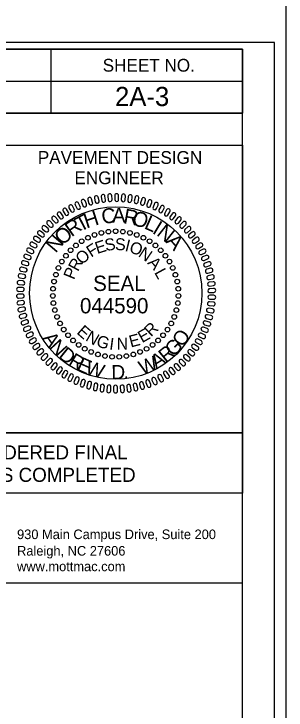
# Model space of a CAD drawing. Extents: x 1901718 to 1902220, y 193828 to 194187.
# Drawn here: x 1902123.6 to 1902134.24, y 193909.67 to 193936.89 of the extents above; entities that cross this region are included whole.
import ezdxf

# ---------------------------------------------------------------- set-up
doc = ezdxf.new("R2010")
doc.units = 0
for name, color, linetype in [('Default', 7, 'Continuous'), ('Old_Level_2', 7, 'Continuous'), ('Old_Level_42', 7, 'Continuous'), ('Scratch_Level_3', 7, 'Continuous'), ('Sheet Border Standard 30in CELL', 7, 'Continuous'), ('Sheet Data Field CELL', 7, 'Continuous'), ('Sheet Plot Border Inside CELL', 7, 'Continuous'), ('Sheet Plot Border Outside CELL', 7, 'Continuous'), ('Sheet Sticker Exception Certification CELL', 7, 'Continuous')]:
    doc.layers.add(name, color=color, linetype=linetype)

msp = doc.modelspace()

# ---------------------------------------------------------------- linework, layer by layer
at = {"layer": 'Default'}
for p, q in [((1902126.493, 193929.622), (1902126.535, 193929.479)), ((1902126.681, 193929.523), (1902126.638, 193929.667)), ((1902126.75, 193929.691), (1902126.784, 193929.545)), ((1902126.932, 193929.579), (1902126.898, 193929.724)), ((1902127.012, 193929.741), (1902127.035, 193929.593)), ((1902127.185, 193929.616), (1902127.162, 193929.764)), ((1902127.277, 193929.772), (1902127.289, 193929.623)), ((1902127.441, 193929.636), (1902127.428, 193929.786)), ((1902127.543, 193929.786), (1902127.545, 193929.636)), ((1902127.697, 193929.638), (1902127.695, 193929.788)), ((1902127.809, 193929.78), (1902127.801, 193929.631)), ((1902127.953, 193929.622), (1902127.961, 193929.772)), ((1902128.074, 193929.756), (1902128.056, 193929.608)), ((1902128.207, 193929.589), (1902128.225, 193929.737)), ((1902128.338, 193929.714), (1902128.308, 193929.567)), ((1902128.458, 193929.537), (1902128.487, 193929.685)), ((1902128.598, 193929.653), (1902128.558, 193929.509)), ((1902128.705, 193929.469), (1902128.744, 193929.614)), ((1902125.962, 193929.255), (1902125.89, 193929.386)), ((1902125.995, 193929.433), (1902126.058, 193929.297)), ((1902126.196, 193929.361), (1902126.132, 193929.497)), ((1902126.24, 193929.536), (1902126.294, 193929.396)), ((1902126.435, 193929.451), (1902126.383, 193929.591)), ((1902128.852, 193929.575), (1902128.803, 193929.433)), ((1902128.946, 193929.383), (1902128.996, 193929.525)), ((1902129.101, 193929.479), (1902129.042, 193929.34)), ((1902129.181, 193929.281), (1902129.241, 193929.418)), ((1902129.342, 193929.365), (1902129.274, 193929.232)), ((1902125.52, 193928.995), (1902125.431, 193929.115)), ((1902125.52, 193928.995), (1902125.431, 193929.115)), ((1902125.528, 193929.176), (1902125.609, 193929.05)), ((1902125.528, 193929.176), (1902125.609, 193929.05)), ((1902125.737, 193929.133), (1902125.656, 193929.259)), ((1902125.737, 193929.133), (1902125.656, 193929.259)), ((1902125.756, 193929.313), (1902125.829, 193929.181)), ((1902129.408, 193929.162), (1902129.477, 193929.295)), ((1902129.574, 193929.235), (1902129.497, 193929.107)), ((1902129.627, 193929.028), (1902129.705, 193929.156)), ((1902129.797, 193929.089), (1902129.712, 193928.966)), ((1902125.101, 193928.857), (1902125.2, 193928.744)), ((1902125.101, 193928.857), (1902125.2, 193928.744)), ((1902125.314, 193928.842), (1902125.216, 193928.957)), ((1902125.314, 193928.842), (1902125.216, 193928.957)), ((1902125.309, 193929.024), (1902125.399, 193928.904)), ((1902125.309, 193929.024), (1902125.399, 193928.904)), ((1902129.835, 193928.879), (1902129.922, 193929.001)), ((1902130.01, 193928.928), (1902129.915, 193928.812)), ((1902130.033, 193928.716), (1902130.128, 193928.832)), ((1902124.936, 193928.497), (1902124.824, 193928.596)), ((1902124.906, 193928.675), (1902125.011, 193928.57)), ((1902125.12, 193928.676), (1902125.014, 193928.783)), ((1902130.211, 193928.753), (1902130.108, 193928.643)), ((1902130.219, 193928.539), (1902130.322, 193928.649)), ((1902130.399, 193928.564), (1902130.288, 193928.462)), ((1902124.556, 193928.274), (1902124.675, 193928.184)), ((1902124.766, 193928.305), (1902124.647, 193928.396)), ((1902124.724, 193928.481), (1902124.836, 193928.383)), ((1902130.392, 193928.35), (1902130.502, 193928.452)), ((1902130.573, 193928.362), (1902130.456, 193928.268)), ((1902124.402, 193928.057), (1902124.527, 193927.975)), ((1902124.611, 193928.102), (1902124.485, 193928.184)), ((1902130.551, 193928.15), (1902130.668, 193928.244)), ((1902130.733, 193928.149), (1902130.609, 193928.063)), ((1902130.697, 193927.938), (1902130.819, 193928.024)), ((1902124.342, 193927.666), (1902124.207, 193927.729)), ((1902124.264, 193927.828), (1902124.395, 193927.756)), ((1902124.469, 193927.888), (1902124.338, 193927.961)), ((1902130.877, 193927.925), (1902130.749, 193927.848)), ((1902130.826, 193927.718), (1902130.955, 193927.794)), ((1902124.232, 193927.434), (1902124.092, 193927.488)), ((1902124.142, 193927.591), (1902124.277, 193927.528)), ((1902131.006, 193927.691), (1902130.872, 193927.624)), ((1902130.94, 193927.488), (1902131.074, 193927.556)), ((1902131.118, 193927.45), (1902130.979, 193927.391)), ((1902124.138, 193927.196), (1902123.995, 193927.24)), ((1902124.038, 193927.346), (1902124.177, 193927.292)), ((1902131.038, 193927.251), (1902131.177, 193927.31)), ((1902131.212, 193927.2), (1902131.07, 193927.152)), ((1902124.061, 193926.951), (1902123.915, 193926.985)), ((1902123.95, 193927.095), (1902124.093, 193927.05)), ((1902131.12, 193927.008), (1902131.262, 193927.056)), ((1902131.289, 193926.945), (1902131.144, 193926.907)), ((1902124.001, 193926.702), (1902123.852, 193926.726)), ((1902123.88, 193926.837), (1902124.026, 193926.803)), ((1902131.183, 193926.76), (1902131.328, 193926.799)), ((1902131.349, 193926.685), (1902131.202, 193926.657)), ((1902123.958, 193926.45), (1902123.809, 193926.463)), ((1902123.829, 193926.576), (1902123.977, 193926.552)), ((1902131.231, 193926.508), (1902131.377, 193926.536)), ((1902131.39, 193926.422), (1902131.241, 193926.404)), ((1902123.933, 193926.194), (1902123.784, 193926.197)), ((1902123.796, 193926.312), (1902123.944, 193926.298)), ((1902131.259, 193926.253), (1902131.408, 193926.271)), ((1902131.413, 193926.156), (1902131.263, 193926.149)), ((1902123.926, 193925.938), (1902123.777, 193925.931)), ((1902123.78, 193926.046), (1902123.93, 193926.042)), ((1902131.416, 193925.89), (1902131.266, 193925.893)), ((1902131.27, 193925.997), (1902131.42, 193926.005)), ((1902123.784, 193925.779), (1902123.934, 193925.786)), ((1902123.938, 193925.682), (1902123.789, 193925.664)), ((1902123.807, 193925.513), (1902123.956, 193925.531)), ((1902131.401, 193925.624), (1902131.252, 193925.638)), ((1902131.263, 193925.741), (1902131.413, 193925.738)), ((1902123.966, 193925.428), (1902123.819, 193925.4)), ((1902123.848, 193925.25), (1902123.995, 193925.278)), ((1902131.368, 193925.359), (1902131.22, 193925.383)), ((1902131.238, 193925.486), (1902131.387, 193925.472)), ((1902124.013, 193925.175), (1902123.868, 193925.137)), ((1902123.907, 193924.99), (1902124.052, 193925.028)), ((1902131.136, 193924.984), (1902131.282, 193924.95)), ((1902131.316, 193925.098), (1902131.17, 193925.132)), ((1902131.195, 193925.233), (1902131.344, 193925.21)), ((1902124.078, 193924.927), (1902123.935, 193924.879)), ((1902123.984, 193924.735), (1902124.126, 193924.783)), ((1902131.058, 193924.739), (1902131.202, 193924.695)), ((1902131.246, 193924.84), (1902131.104, 193924.885)), ((1902124.158, 193924.684), (1902124.02, 193924.626)), ((1902124.079, 193924.485), (1902124.217, 193924.544)), ((1902124.256, 193924.447), (1902124.122, 193924.379)), ((1902130.964, 193924.501), (1902131.104, 193924.447)), ((1902131.159, 193924.589), (1902131.019, 193924.643)), ((1902124.191, 193924.244), (1902124.325, 193924.311)), ((1902124.371, 193924.218), (1902124.242, 193924.141)), ((1902130.933, 193924.107), (1902130.802, 193924.18)), ((1902130.854, 193924.27), (1902130.99, 193924.206)), ((1902131.054, 193924.344), (1902130.919, 193924.407)), ((1902124.32, 193924.01), (1902124.448, 193924.087)), ((1902124.5, 193923.997), (1902124.377, 193923.911)), ((1902130.795, 193923.878), (1902130.669, 193923.96)), ((1902130.728, 193924.047), (1902130.859, 193923.973)), ((1902124.464, 193923.786), (1902124.587, 193923.872)), ((1902124.645, 193923.785), (1902124.529, 193923.692)), ((1902124.623, 193923.573), (1902124.741, 193923.667)), ((1902130.43, 193923.63), (1902130.549, 193923.54)), ((1902130.641, 193923.661), (1902130.522, 193923.751)), ((1902130.586, 193923.833), (1902130.711, 193923.751)), ((1902124.804, 193923.585), (1902124.695, 193923.483)), ((1902124.798, 193923.372), (1902124.908, 193923.474)), ((1902124.978, 193923.396), (1902124.875, 193923.287)), ((1902130.291, 193923.26), (1902130.185, 193923.366)), ((1902130.26, 193923.438), (1902130.373, 193923.34)), ((1902130.473, 193923.454), (1902130.36, 193923.553)), ((1902124.986, 193923.182), (1902125.089, 193923.292)), ((1902125.164, 193923.219), (1902125.069, 193923.103)), ((1902125.187, 193923.007), (1902125.281, 193923.123)), ((1902129.882, 193923.092), (1902129.98, 193922.979)), ((1902130.095, 193923.079), (1902129.997, 193923.192)), ((1902130.077, 193923.259), (1902130.182, 193923.153)), ((1902125.361, 193923.056), (1902125.274, 193922.934)), ((1902125.399, 193922.846), (1902125.485, 193922.969)), ((1902125.57, 193922.907), (1902125.492, 193922.779)), ((1902125.622, 193922.701), (1902125.699, 193922.828)), ((1902129.669, 193922.759), (1902129.587, 193922.885)), ((1902129.676, 193922.94), (1902129.766, 193922.82)), ((1902129.888, 193922.912), (1902129.797, 193923.031)), ((1902125.788, 193922.773), (1902125.72, 193922.64)), ((1902125.855, 193922.57), (1902125.924, 193922.704)), ((1902126.016, 193922.655), (1902125.956, 193922.516)), ((1902126.096, 193922.457), (1902126.155, 193922.595)), ((1902126.25, 193922.552), (1902126.201, 193922.411)), ((1902128.957, 193922.399), (1902128.903, 193922.539)), ((1902129.001, 193922.575), (1902129.064, 193922.439)), ((1902129.202, 193922.502), (1902129.139, 193922.638)), ((1902129.235, 193922.68), (1902129.307, 193922.549)), ((1902129.44, 193922.623), (1902129.368, 193922.754)), ((1902129.46, 193922.803), (1902129.541, 193922.677)), ((1902126.345, 193922.36), (1902126.394, 193922.503)), ((1902126.492, 193922.467), (1902126.453, 193922.322)), ((1902126.599, 193922.282), (1902126.638, 193922.427)), ((1902126.739, 193922.397), (1902126.71, 193922.251)), ((1902126.859, 193922.221), (1902126.888, 193922.368)), ((1902126.99, 193922.346), (1902126.971, 193922.198)), ((1902127.122, 193922.179), (1902127.141, 193922.327)), ((1902127.244, 193922.313), (1902127.236, 193922.163)), ((1902127.387, 193922.155), (1902127.396, 193922.305)), ((1902127.499, 193922.297), (1902127.502, 193922.147)), ((1902127.654, 193922.15), (1902127.652, 193922.3)), ((1902127.756, 193922.299), (1902127.769, 193922.15)), ((1902127.92, 193922.163), (1902127.908, 193922.312)), ((1902128.012, 193922.319), (1902128.034, 193922.171)), ((1902128.185, 193922.195), (1902128.162, 193922.343)), ((1902128.265, 193922.357), (1902128.298, 193922.21)), ((1902128.447, 193922.245), (1902128.413, 193922.391)), ((1902128.515, 193922.412), (1902128.558, 193922.269)), ((1902128.704, 193922.313), (1902128.661, 193922.456)), ((1902128.761, 193922.485), (1902128.814, 193922.344))]:
    msp.add_line(p, q, dxfattribs=at)
for centre in [(1902126.754, 193928.252), (1902127.023, 193928.331), (1902127.3, 193928.378), (1902127.58, 193928.394), (1902127.861, 193928.378), (1902128.137, 193928.33), (1902128.406, 193928.251), (1902126.252, 193928.004), (1902126.496, 193928.142), (1902128.665, 193928.142), (1902128.909, 193928.004), (1902125.818, 193927.65), (1902126.025, 193927.839), (1902129.136, 193927.839), (1902129.343, 193927.649), (1902125.634, 193927.438), (1902129.526, 193927.437), (1902125.476, 193927.206), (1902129.685, 193927.206), (1902125.345, 193926.958), (1902129.815, 193926.958), (1902125.243, 193926.697), (1902129.917, 193926.696), (1902125.172, 193926.425), (1902129.988, 193926.425), (1902125.132, 193926.148), (1902130.028, 193926.147), (1902125.124, 193925.867), (1902130.036, 193925.867), (1902125.148, 193925.588), (1902130.012, 193925.587), (1902125.203, 193925.313), (1902129.956, 193925.312), (1902125.29, 193925.046), (1902129.87, 193925.045), (1902125.407, 193924.791), (1902129.753, 193924.79), (1902125.551, 193924.55), (1902129.608, 193924.55), (1902125.723, 193924.328), (1902125.918, 193924.127), (1902129.241, 193924.127), (1902129.437, 193924.328), (1902126.135, 193923.949), (1902129.024, 193923.949), (1902126.371, 193923.798), (1902126.623, 193923.674), (1902126.887, 193923.579), (1902128.272, 193923.579), (1902128.536, 193923.674), (1902128.788, 193923.797), (1902127.161, 193923.516), (1902127.439, 193923.484), (1902127.72, 193923.484), (1902127.999, 193923.516)]:
    msp.add_circle(centre, 0.091, dxfattribs=at)
for centre, start, end in [((1902126.311, 193929.563), 20.8349, 200.8343), ((1902126.565, 193929.645), 16.8349, 196.8343), ((1902126.824, 193929.708), 12.8349, 192.8343), ((1902127.087, 193929.753), 8.8349, 188.8343), ((1902127.11, 193929.604), 188.8343, 8.8349), ((1902127.352, 193929.779), 4.8349, 184.8343), ((1902127.365, 193929.63), 184.8343, 4.8349), ((1902127.619, 193929.787), 0.8349, 180.8343), ((1902127.621, 193929.637), 180.8343, 0.8349), ((1902127.877, 193929.626), 176.8343, 356.8349), ((1902127.885, 193929.776), 356.8349, 176.8343), ((1902128.15, 193929.747), 352.8349, 172.8343), ((1902128.412, 193929.699), 348.8349, 168.8343), ((1902128.671, 193929.633), 344.8349, 164.8343), ((1902128.924, 193929.55), 340.8349, 160.8343), ((1902125.823, 193929.349), 28.8349, 208.8343), ((1902126.064, 193929.465), 24.8349, 204.8343), ((1902126.126, 193929.329), 204.8343, 24.8349), ((1902126.365, 193929.423), 200.8343, 20.8349), ((1902126.609, 193929.501), 196.8343, 16.8349), ((1902126.857, 193929.561), 192.8343, 12.8349), ((1902128.131, 193929.598), 172.8343, 352.8349), ((1902128.383, 193929.552), 168.8343, 348.8349), ((1902128.631, 193929.489), 164.8343, 344.8349), ((1902128.875, 193929.408), 160.8343, 340.8349), ((1902129.111, 193929.311), 156.8343, 336.8349), ((1902129.17, 193929.448), 336.8349, 156.8343), ((1902129.409, 193929.33), 332.8349, 152.8343), ((1902125.37, 193929.069), 36.8349, 216.8343), ((1902125.37, 193929.069), 36.8349, 216.8343), ((1902125.592, 193929.217), 32.8349, 212.8343), ((1902125.592, 193929.217), 32.8349, 212.8343), ((1902125.673, 193929.091), 212.8343, 32.8349), ((1902125.673, 193929.091), 212.8343, 32.8349), ((1902125.896, 193929.218), 208.8343, 28.8349), ((1902129.341, 193929.197), 152.8343, 332.8349), ((1902129.562, 193929.067), 148.8343, 328.8349), ((1902129.64, 193929.196), 328.8349, 148.8343), ((1902129.86, 193929.045), 324.8349, 144.8343), ((1902124.96, 193928.729), 44.8349, 224.8343), ((1902125.159, 193928.906), 40.8349, 220.8343), ((1902125.159, 193928.906), 40.8349, 220.8343), ((1902125.257, 193928.793), 220.8343, 40.8349), ((1902125.257, 193928.793), 220.8343, 40.8349), ((1902125.46, 193928.949), 216.8343, 36.8349), ((1902125.46, 193928.949), 216.8343, 36.8349), ((1902129.773, 193928.923), 144.8343, 324.8349), ((1902129.974, 193928.764), 140.8343, 320.8349), ((1902130.069, 193928.88), 320.8349, 140.8343), ((1902124.774, 193928.538), 48.8349, 228.8343), ((1902125.066, 193928.623), 224.8343, 44.8349), ((1902130.164, 193928.591), 136.8343, 316.8349), ((1902130.266, 193928.701), 316.8349, 136.8343), ((1902130.45, 193928.508), 312.8349, 132.8343), ((1902124.601, 193928.335), 52.8349, 232.8343), ((1902124.721, 193928.244), 232.8343, 52.8349), ((1902124.887, 193928.44), 228.8343, 48.8349), ((1902130.34, 193928.406), 132.8343, 312.8349), ((1902130.504, 193928.209), 128.8343, 308.8349), ((1902130.62, 193928.303), 308.8349, 128.8343), ((1902124.443, 193928.12), 56.8349, 236.8343), ((1902124.569, 193928.038), 236.8343, 56.8349), ((1902130.653, 193928.001), 124.8343, 304.8349), ((1902130.776, 193928.086), 304.8349, 124.8343), ((1902124.174, 193927.66), 64.8349, 244.8343), ((1902124.301, 193927.895), 60.8349, 240.8343), ((1902124.432, 193927.822), 240.8343, 60.8349), ((1902130.787, 193927.783), 120.8343, 300.8349), ((1902130.916, 193927.86), 300.8349, 120.8343), ((1902124.065, 193927.417), 68.8349, 248.8343), ((1902124.205, 193927.363), 248.8343, 68.8349), ((1902124.31, 193927.596), 244.8343, 64.8349), ((1902130.906, 193927.556), 116.8343, 296.8349), ((1902131.04, 193927.623), 296.8349, 116.8343), ((1902131.147, 193927.379), 292.8349, 112.8343), ((1902123.972, 193927.167), 72.8349, 252.8343), ((1902124.115, 193927.123), 252.8343, 72.8349), ((1902131.009, 193927.321), 112.8343, 292.8349), ((1902131.237, 193927.128), 288.8349, 108.8343), ((1902123.897, 193926.911), 76.8349, 256.8343), ((1902124.043, 193926.877), 256.8343, 76.8349), ((1902131.095, 193927.08), 108.8343, 288.8349), ((1902131.164, 193926.833), 104.8343, 284.8349), ((1902131.309, 193926.872), 284.8349, 104.8343), ((1902123.841, 193926.651), 80.8349, 260.8343), ((1902123.989, 193926.627), 260.8343, 80.8349), ((1902131.216, 193926.582), 100.8343, 280.8349), ((1902131.363, 193926.611), 280.8349, 100.8343), ((1902123.802, 193926.387), 84.8349, 264.8343), ((1902123.951, 193926.374), 264.8343, 84.8349), ((1902131.25, 193926.329), 96.8343, 276.8349), ((1902131.399, 193926.346), 276.8349, 96.8343), ((1902123.782, 193926.121), 88.8349, 268.8343), ((1902123.932, 193926.118), 268.8343, 88.8349), ((1902131.266, 193926.073), 92.8343, 272.8349), ((1902131.416, 193926.08), 272.8349, 92.8343), ((1902123.781, 193925.855), 92.8349, 272.8343), ((1902123.93, 193925.862), 272.8343, 92.8349), ((1902131.265, 193925.817), 88.8343, 268.8349), ((1902131.415, 193925.814), 268.8349, 88.8343), ((1902123.798, 193925.589), 96.8349, 276.8343), ((1902123.947, 193925.607), 276.8343, 96.8349), ((1902131.245, 193925.562), 84.8343, 264.8349), ((1902131.394, 193925.548), 264.8349, 84.8343), ((1902123.833, 193925.324), 100.8349, 280.8343), ((1902123.981, 193925.353), 280.8343, 100.8349), ((1902131.208, 193925.308), 80.8343, 260.8349), ((1902131.356, 193925.284), 260.8349, 80.8343), ((1902123.888, 193925.063), 104.8349, 284.8343), ((1902124.032, 193925.102), 284.8343, 104.8349), ((1902131.153, 193925.058), 76.8343, 256.8349), ((1902131.299, 193925.024), 256.8349, 76.8343), ((1902123.96, 193924.807), 108.8349, 288.8343), ((1902124.101, 193924.855), 288.8343, 108.8349), ((1902131.081, 193924.812), 72.8343, 252.8349), ((1902131.224, 193924.768), 252.8349, 72.8343), ((1902124.049, 193924.556), 112.8349, 292.8343), ((1902124.188, 193924.614), 292.8343, 112.8349), ((1902124.29, 193924.379), 296.8343, 116.8349), ((1902130.992, 193924.572), 68.8343, 248.8349), ((1902131.132, 193924.518), 248.8349, 68.8343), ((1902124.157, 193924.312), 116.8349, 296.8343), ((1902124.409, 193924.152), 300.8343, 120.8349), ((1902130.765, 193924.113), 60.8343, 240.8349), ((1902130.886, 193924.339), 64.8343, 244.8349), ((1902131.022, 193924.275), 244.8349, 64.8343), ((1902124.28, 193924.076), 120.8349, 300.8343), ((1902124.421, 193923.849), 124.8349, 304.8343), ((1902124.544, 193923.934), 304.8343, 124.8349), ((1902130.628, 193923.897), 56.8343, 236.8349), ((1902130.896, 193924.04), 240.8349, 60.8343), ((1902124.576, 193923.632), 128.8349, 308.8343), ((1902124.693, 193923.726), 308.8343, 128.8349), ((1902130.476, 193923.691), 52.8343, 232.8349), ((1902130.595, 193923.6), 232.8349, 52.8343), ((1902130.753, 193923.815), 236.8349, 56.8343), ((1902124.746, 193923.427), 132.8349, 312.8343), ((1902124.856, 193923.529), 312.8343, 132.8349), ((1902125.033, 193923.344), 316.8343, 136.8349), ((1902130.131, 193923.312), 44.8343, 224.8349), ((1902130.31, 193923.495), 48.8343, 228.8349), ((1902130.423, 193923.397), 228.8349, 48.8343), ((1902124.93, 193923.234), 136.8349, 316.8343), ((1902125.128, 193923.055), 140.8349, 320.8343), ((1902125.222, 193923.171), 320.8343, 140.8349), ((1902125.423, 193923.012), 324.8343, 144.8349), ((1902129.94, 193923.142), 40.8343, 220.8349), ((1902130.038, 193923.029), 220.8349, 40.8343), ((1902130.237, 193923.206), 224.8349, 44.8343), ((1902125.337, 193922.89), 144.8349, 324.8343), ((1902125.635, 193922.868), 328.8343, 148.8349), ((1902125.856, 193922.738), 332.8343, 152.8349), ((1902129.524, 193922.844), 32.8343, 212.8349), ((1902129.737, 193922.986), 36.8343, 216.8349), ((1902129.827, 193922.866), 216.8349, 36.8343), ((1902125.557, 193922.739), 148.8349, 328.8343), ((1902125.787, 193922.605), 152.8349, 332.8343), ((1902126.085, 193922.625), 336.8343, 156.8349), ((1902126.322, 193922.527), 340.8343, 160.8349), ((1902128.832, 193922.512), 20.8343, 200.8349), ((1902129.07, 193922.606), 24.8343, 204.8349), ((1902129.301, 193922.717), 28.8343, 208.8349), ((1902129.373, 193922.586), 208.8349, 28.8343), ((1902129.605, 193922.718), 212.8349, 32.8343), ((1902126.026, 193922.487), 156.8349, 336.8343), ((1902126.273, 193922.386), 160.8349, 340.8343), ((1902126.526, 193922.302), 164.8349, 344.8343), ((1902126.565, 193922.447), 344.8343, 164.8349), ((1902126.813, 193922.383), 348.8343, 168.8349), ((1902127.065, 193922.337), 352.8343, 172.8349), ((1902127.32, 193922.309), 356.8343, 176.8349), ((1902127.576, 193922.298), 0.8343, 180.8349), ((1902127.832, 193922.306), 4.8343, 184.8349), ((1902128.087, 193922.331), 8.8343, 188.8349), ((1902128.339, 193922.374), 12.8343, 192.8349), ((1902128.588, 193922.434), 16.8343, 196.8349), ((1902128.631, 193922.291), 196.8349, 16.8343), ((1902128.885, 193922.372), 200.8349, 20.8343), ((1902129.133, 193922.47), 204.8349, 24.8343), ((1902126.784, 193922.236), 168.8349, 348.8343), ((1902127.047, 193922.188), 172.8349, 352.8343), ((1902127.311, 193922.159), 176.8349, 356.8343), ((1902127.578, 193922.148), 180.8349, 0.8343), ((1902127.844, 193922.156), 184.8349, 4.8343), ((1902128.11, 193922.183), 188.8349, 8.8343), ((1902128.372, 193922.228), 192.8349, 12.8343)]:
    msp.add_arc(centre, 0.0761, start, end, dxfattribs=at)
at = {"layer": 'Old_Level_42'}
msp.add_lwpolyline([(1902132.544, 193914.629), (1902112.539, 193914.629), (1902112.539, 193918.159)], dxfattribs=at)
at = {"layer": 'Scratch_Level_3'}
msp.add_circle((1902127.586, 193925.977), 3.37, dxfattribs=at)
at = {"layer": 'Sheet Border Standard 30in CELL'}
for p, q in [((1902125.044, 193935.509), (1902125.044, 193933.009)), ((1902112.539, 193934.259), (1902132.544, 193934.259)), ((1902112.539, 193933.009), (1902132.544, 193933.009)), ((1902112.539, 193933.009), (1902132.544, 193933.009))]:
    msp.add_line(p, q, dxfattribs=at)
for points in [[(1902132.544, 193935.514), (1901982.544, 193935.514), (1901982.544, 193830.514), (1902132.544, 193830.514)], [(1902112.539, 193935.514), (1902132.544, 193935.514), (1902132.544, 193933.009), (1902112.539, 193933.009)], [(1902122.544, 193931.759), (1902132.544, 193931.759), (1902132.544, 193920.509), (1902122.544, 193920.509)]]:
    msp.add_lwpolyline(points, close=True, dxfattribs=at)
at = {"layer": 'Sheet Plot Border Inside CELL'}
msp.add_lwpolyline([(1902133.794, 193935.769), (1901967.144, 193935.769), (1901967.144, 193830.259), (1902133.794, 193830.259)], close=True, dxfattribs=at)
at = {"layer": 'Sheet Plot Border Outside CELL'}
msp.add_lwpolyline([(1902134.244, 193938.014), (1901965.844, 193938.014), (1901965.844, 193828.014), (1902134.244, 193828.014)], close=True, dxfattribs=at)
at = {"layer": 'Sheet Sticker Exception Certification CELL'}
for p, q in [((1902112.539, 193920.509), (1902132.542, 193920.509)), ((1902132.542, 193920.508), (1902132.542, 193918.158)), ((1902132.542, 193918.159), (1902112.539, 193918.159))]:
    msp.add_line(p, q, dxfattribs=at)

# ---------------------------------------------------------------- texts
at = {"layer": 'Default'}
for s, height, rotation, p in [('T', 0.582, 27.6116, (1902126.191, 193928.354)), ('H', 0.582, 17.8424, (1902126.438, 193928.5)), ('C', 0.582, 7.9778, (1902127.067, 193928.673)), ('A', 0.582, 0.1945, (1902127.447, 193928.727)), ('R', 0.582, 349.6661, (1902127.858, 193928.712)), ('O', 0.582, 345.727, (1902128.188, 193928.647)), ('R', 0.582, 35.4408, (1902125.857, 193928.153)), ('L', 0.582, 336.5157, (1902128.661, 193928.515)), ('I', 0.582, 328.9592, (1902128.98, 193928.337)), ('O', 0.582, 42.8836, (1902125.508, 193927.816)), ('N', 0.582, 321.6624, (1902129.148, 193928.257)), ('N', 0.582, 49.6124, (1902125.233, 193927.517)), ('E', 0.467, 17.5898, (1902126.86, 193927.503)), ('S', 0.467, 10.2172, (1902127.196, 193927.614)), ('S', 0.467, 359.0087, (1902127.553, 193927.656)), ('I', 0.467, 346.1383, (1902127.917, 193927.629)), ('O', 0.467, 340.1508, (1902128.08, 193927.587)), ('A', 0.582, 312.1327, (1902129.517, 193927.979)), ('F', 0.467, 32.3349, (1902126.623, 193927.358)), ('N', 0.467, 326.0425, (1902128.432, 193927.43)), ('O', 0.467, 40.6085, (1902126.256, 193927.067)), ('R', 0.467, 61.8256, (1902126.11, 193926.794)), ('A', 0.467, 312.7467, (1902128.803, 193927.144)), ('P', 0.467, 68.0589, (1902125.951, 193926.476)), ('L', 0.467, 298.716, (1902129.08, 193926.784)), ('SEAL', 0.5992, 360, (1902126.701, 193926.059)), ('E', 0.467, 318.6101, (1902126.03, 193924.416)), ('R', 0.467, 44.0241, (1902128.967, 193924.243)), ('N', 0.467, 329.8446, (1902126.372, 193924.138)), ('E', 0.467, 29.2789, (1902128.613, 193924.017)), ('O', 0.56, 54.3575, (1902130.196, 193923.834)), ('A', 0.56, 305.2118, (1902124.706, 193924.213)), ('N', 0.56, 312.6812, (1902124.959, 193923.854)), ('G', 0.467, 342.6124, (1902126.792, 193923.908)), ('I', 0.467, 352.4162, (1902127.315, 193923.773)), ('N', 0.467, 359.7887, (1902127.615, 193923.767)), ('E', 0.467, 14.5337, (1902128.171, 193923.847)), ('R', 0.56, 39.0595, (1902129.539, 193923.222)), ('G', 0.56, 45.5995, (1902129.84, 193923.462)), ('D', 0.56, 321.4392, (1902125.313, 193923.479)), ('R', 0.56, 329.6163, (1902125.692, 193923.181)), ('E', 0.56, 336.1564, (1902126.022, 193922.983)), ('W', 0.56, 342.4429, (1902126.36, 193922.83)), ('W', 0.56, 21.5963, (1902128.622, 193922.762)), ('A', 0.56, 31.59, (1902129.164, 193922.991)), ('D', 0.56, 0.8355, (1902127.415, 193922.604)), ('.', 0.56, 9.0126, (1902127.897, 193922.614))]:
    msp.add_text(s, height=height, rotation=rotation, dxfattribs=at).set_placement(p)
msp.add_text('044590', height=0.5994, dxfattribs=at).set_placement((1902126.186, 193925.184))
at = {"layer": 'Old_Level_2'}
for s, p in [('930 Main Campus Drive, Suite 200', (1902123.726, 193916.357)), ('Raleigh, NC 27606', (1902123.726, 193915.712)), ('www.mottmac.com', (1902123.726, 193915.103))]:
    msp.add_text(s, height=0.375, rotation=360, dxfattribs=at).set_placement(p)
at = {"layer": 'Sheet Border Standard 30in CELL'}
for s, height, p in [('SHEET NO.', 0.5, (1902127.074, 193934.634)), ('PAVEMENT DESIGN', 0.50001, (1902124.538, 193931.029)), ('ENGINEER', 0.5, (1902125.969, 193930.234))]:
    msp.add_text(s, height=height, dxfattribs=at).set_placement(p)
at = {"layer": 'Sheet Data Field CELL'}
msp.add_text('2A-3', height=0.75, dxfattribs=at).set_placement((1902127.557, 193933.289))
at = {"layer": 'Sheet Sticker Exception Certification CELL'}
for s, p in [('DOCUMENT NOT CONSIDERED FINAL', (1902114.646, 193919.475)), ('UNLESS ALL SIGNATURES COMPLETED', (1902114.139, 193918.595))]:
    msp.add_text(s, height=0.55, dxfattribs=at).set_placement(p)

doc.saveas('drawing.dxf')
